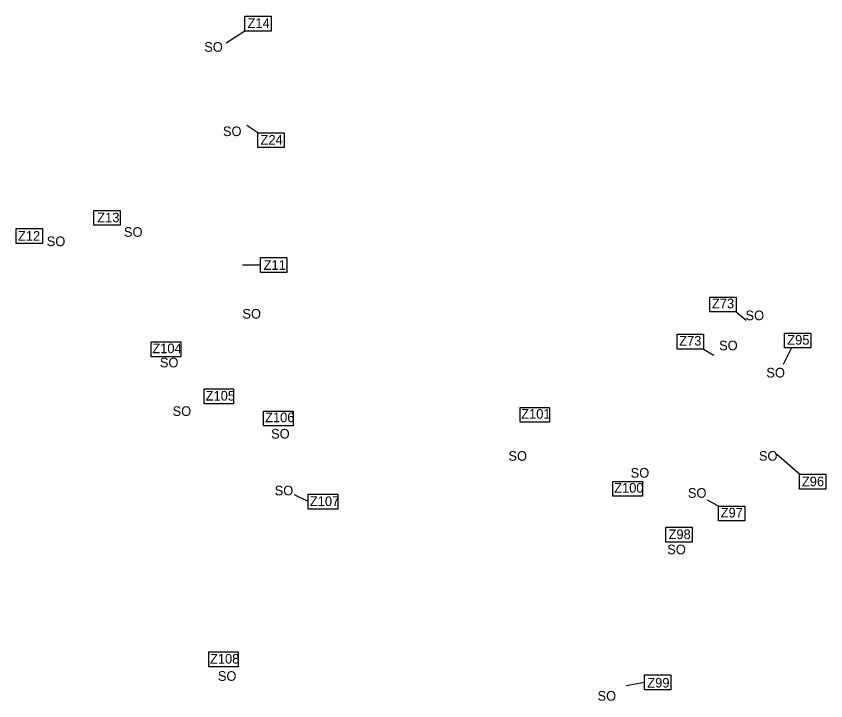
# Model space of a CAD drawing. Extents: x -443519 to -431242, y -1133468 to -1129615.
# Drawn here: x -442867 to -442026, y -1132385 to -1131674 of the extents above; entities that cross this region are included whole.
import ezdxf

# ---------------------------------------------------------------- set-up
doc = ezdxf.new("R2010")
doc.units = 0
doc.layers.add('Vrstva 3', color=7, linetype='Continuous')
doc.layers.add('Vrstva 4', color=7, linetype='Continuous')

msp = doc.modelspace()

# ---------------------------------------------------------------- linework, layer by layer
at = {"layer": 'Vrstva 3'}
for p, q in [((-442629.72, -1131689.68), (-442648.9, -1131702.14)), ((-442616.17, -1131795.24), (-442627.54, -1131787.71)), ((-442613.44, -1131932.69), (-442631.82, -1131932.69)), ((-442119.3, -1131981.24), (-442108.96, -1131989.79)), ((-442153.24, -1132019.92), (-442142.74, -1132026.07)), ((-442061.79, -1132018.77), (-442070.53, -1132035.75)), ((-442053.69, -1132149.91), (-442077, -1132129.46)), ((-442563.84, -1132178.3), (-442578.15, -1132171.11)), ((-442137.89, -1132182.85), (-442149.22, -1132176.81)), ((-442214.59, -1132365.99), (-442233.78, -1132369.54))]:
    msp.add_line(p, q, dxfattribs=at)
for points in [[(-442629.72, -1131674.28), (-442602.35, -1131674.28), (-442602.35, -1131689.68), (-442629.72, -1131689.68)], [(-442616.17, -1131795.24), (-442588.8, -1131795.24), (-442588.8, -1131810.64), (-442616.17, -1131810.64)], [(-442786.33, -1131876.02), (-442758.96, -1131876.02), (-442758.96, -1131891.42), (-442786.33, -1131891.42)], [(-442866.96, -1131894.74), (-442839.59, -1131894.74), (-442839.59, -1131910.14), (-442866.96, -1131910.14)], [(-442613.44, -1131924.99), (-442586.07, -1131924.99), (-442586.07, -1131940.39), (-442613.44, -1131940.39)], [(-442146.67, -1131965.84), (-442119.3, -1131965.84), (-442119.3, -1131981.24), (-442146.67, -1131981.24)], [(-442180.61, -1132004.52), (-442153.24, -1132004.52), (-442153.24, -1132019.92), (-442180.61, -1132019.92)], [(-442069.11, -1132003.37), (-442041.74, -1132003.37), (-442041.74, -1132018.77), (-442069.11, -1132018.77)], [(-442726.91, -1132012.52), (-442696.15, -1132012.52), (-442696.15, -1132027.92), (-442726.91, -1132027.92)], [(-442671.95, -1132061.35), (-442641.19, -1132061.35), (-442641.19, -1132076.75), (-442671.95, -1132076.75)], [(-442343.82, -1132080.52), (-442313.06, -1132080.52), (-442313.06, -1132095.92), (-442343.82, -1132095.92)], [(-442610.02, -1132084.36), (-442579.26, -1132084.36), (-442579.26, -1132099.76), (-442610.02, -1132099.76)], [(-442053.69, -1132149.91), (-442026.32, -1132149.91), (-442026.32, -1132165.31), (-442053.69, -1132165.31)], [(-442247.45, -1132157.25), (-442216.69, -1132157.25), (-442216.69, -1132172.65), (-442247.45, -1132172.65)], [(-442563.84, -1132170.6), (-442533.08, -1132170.6), (-442533.08, -1132186), (-442563.84, -1132186)], [(-442137.89, -1132182.85), (-442110.52, -1132182.85), (-442110.52, -1132198.25), (-442137.89, -1132198.25)], [(-442192.5, -1132204.87), (-442165.13, -1132204.87), (-442165.13, -1132220.27), (-442192.5, -1132220.27)], [(-442667.1, -1132334.36), (-442636.34, -1132334.36), (-442636.34, -1132349.76), (-442667.1, -1132349.76)], [(-442214.59, -1132358.29), (-442187.22, -1132358.29), (-442187.22, -1132373.69), (-442214.59, -1132373.69)]]:
    msp.add_lwpolyline(points, close=True, dxfattribs=at)

# ---------------------------------------------------------------- texts
for s, p in [('Z14', (-442626.73, -1131686.45)), ('Z24', (-442613.32, -1131807.59)), ('Z13', (-442782.79, -1131888.32)), ('Z12', (-442865.14, -1131907.37)), ('Z11', (-442610.03, -1131937.67)), ('Z73', (-442144.58, -1131977.59)), ('Z95', (-442066.34, -1132015.35)), ('Z104', (-442725.59, -1132024.16)), ('Z73', (-442178.52, -1132016.27)), ('Z105', (-442670.24, -1132073.35)), ('Z106', (-442608.54, -1132095.81)), ('Z101', (-442342.63, -1132092.22)), ('Z96', (-442051.18, -1132162.36)), ('Z100', (-442246.04, -1132168.99)), ('Z107', (-442562.01, -1132182.85)), ('Z97', (-442135.46, -1132194.74)), ('Z98', (-442189.58, -1132217.19)), ('Z108', (-442665.72, -1132346.44)), ('Z99', (-442211.66, -1132371.35))]:
    msp.add_text(s, height=10, dxfattribs=at).set_placement(p)
at = {"layer": 'Vrstva 4'}
for p in [(-442671.73, -1131711.22), (-442652.31, -1131798.8), (-442755.09, -1131903.33), (-442835.24, -1131912.99), (-442632.1, -1131988.24), (-442109.68, -1131989.92), (-442137.13, -1132021.17), (-442717.78, -1132038.9), (-442088.1, -1132049.39), (-442704.56, -1132089.32), (-442602.34, -1132112.8), (-442355.86, -1132135.86), (-442095.82, -1132135.77), (-442228.97, -1132153.39), (-442598.61, -1132171.76), (-442169.52, -1132174.3), (-442190.97, -1132232.94), (-442657.58, -1132364.34), (-442263.34, -1132384.95)]:
    msp.add_text('SO', height=10, dxfattribs=at).set_placement(p)

doc.saveas('drawing.dxf')
